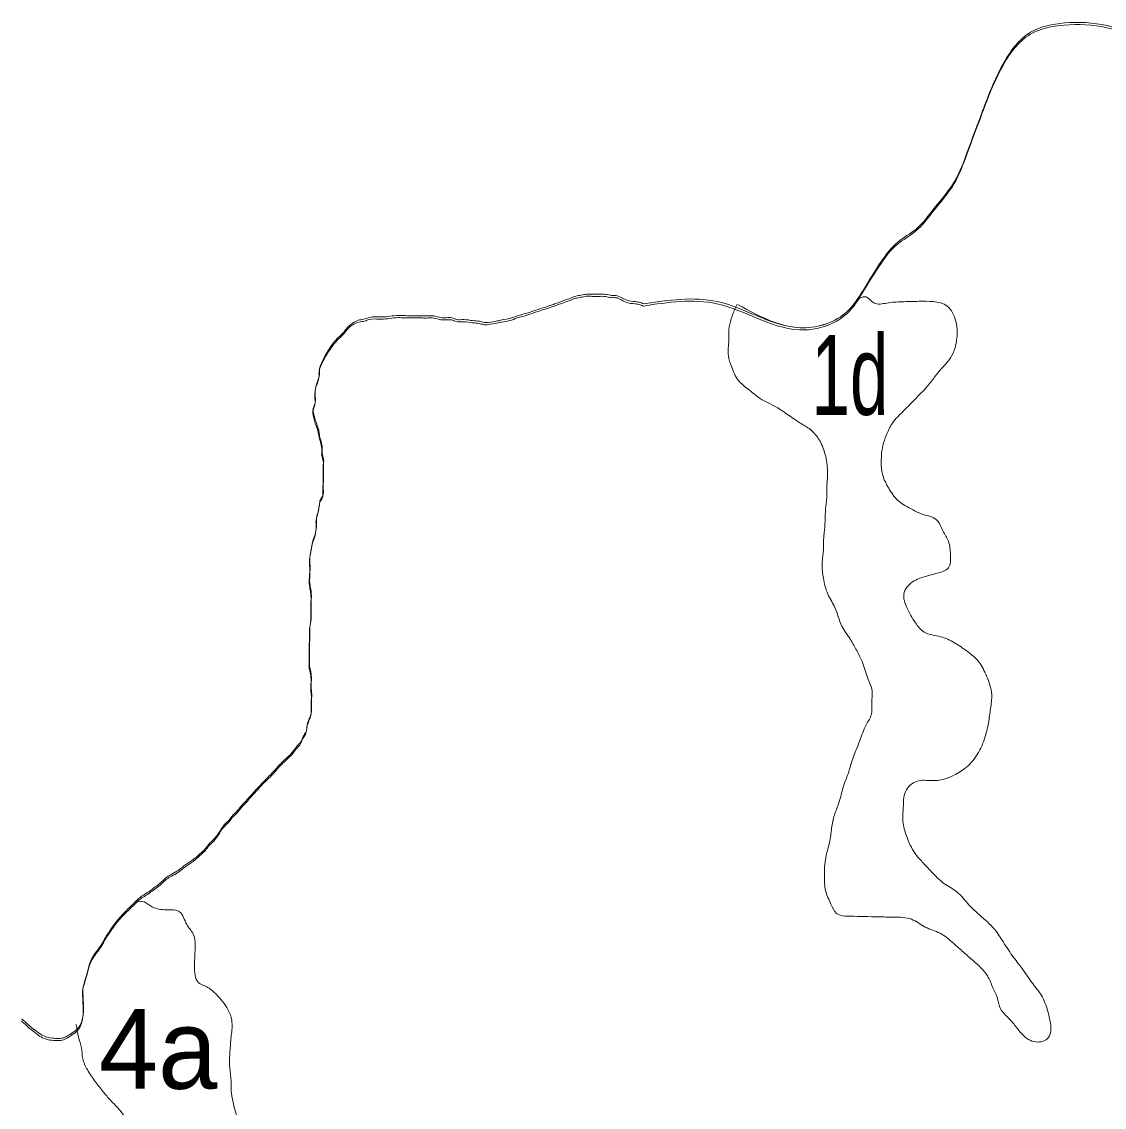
# Model space of a CAD drawing. Extents: x 854879 to 917879, y 8541948 to 8631048.
# Drawn here: x 877509 to 882670, y 8607550 to 8612725 of the extents above; entities that cross this region are included whole.
import ezdxf
from ezdxf.enums import TextEntityAlignment as Align

# ---------------------------------------------------------------- set-up
doc = ezdxf.new("R2010")
doc.units = 0
doc.header["$LTSCALE"] = 150
for name, color, linetype, lineweight in [('12', 7, 'Continuous', 13), ('40', 7, 'Continuous', 13), ('50', 7, 'Continuous', 13), ('59', 7, 'Continuous', 13)]:
    doc.layers.add(name, color=color, linetype=linetype, lineweight=lineweight)

msp = doc.modelspace()

# ---------------------------------------------------------------- linework, layer by layer
at = {"layer": '12'}
for points in [[(883458.2, 8611696.1), (883312.8, 8611690.2), (883254.5, 8611718.9), (883130.1, 8612194.4), (883075.4, 8612309.7), (882992.8, 8612435.6), (882922.5, 8612525.6), (882806.7, 8612646.7), (882682.3, 8612696.7), (882478.6, 8612709.3), (882317.4, 8612665.3), (882183, 8612509), (882088.6, 8612290.9), (882014.9, 8612093.1), (881954.6, 8611953.6), (881858.8, 8611827.3), (881770.9, 8611726.5), (881683.5, 8611663.8), (881605.9, 8611573), (881515, 8611428.8), (881452.8, 8611342.9), (881245.3, 8611256.2), (880823.3, 8611380.8), (880472, 8611369.8)], [(880472, 8611369.8), (880451.7, 8611377.7), (880431.4, 8611380.5), (880395.8, 8611386), (880368, 8611399.1), (880340.2, 8611409.6), (880319.8, 8611409.8), (880291.9, 8611415.2), (880258.8, 8611415.6), (880230.8, 8611415.9), (880200.3, 8611416.3), (880174.8, 8611411.4), (880149.3, 8611406.6), (880123.8, 8611396.7), (880095.6, 8611386.8), (880047.1, 8611369.5), (880026.7, 8611362.1), (880003.7, 8611354.7), (879957.7, 8611339.9), (879921.9, 8611327.6), (879870.8, 8611312.9), (879835.1, 8611300.5), (879796.8, 8611293.3), (879773.9, 8611288.5), (879733.1, 8611281.3), (879710.2, 8611281.5), (879689.9, 8611286.9), (879656.9, 8611289.8), (879616.2, 8611295.3), (879580.6, 8611295.8), (879557.8, 8611303.7), (879532.4, 8611303.9), (879506.9, 8611304.2), (879474, 8611312.2), (879438.3, 8611312.7), (879410.4, 8611313), (879367.1, 8611313.4), (879326.4, 8611313.9), (879293.3, 8611314.3), (879252.6, 8611309.6), (879211.8, 8611307.6), (879166, 8611305.5), (879143, 8611298.1), (879117.5, 8611293.3), (879092, 8611283.4), (879061.1, 8611258.2), (879037.9, 8611230.5), (879009.6, 8611202.7), (878988.9, 8611177.5), (878947.4, 8611111.6), (878934.3, 8611083.7), (878926.3, 8611053.2), (878926.1, 8611030.3), (878912.8, 8610987.1), (878907.4, 8610961.7), (878907, 8610928.5), (878904, 8610890.3), (878896.1, 8610867.4), (878903.3, 8610831.7), (878910.6, 8610803.5), (878922.8, 8610767.7), (878927.6, 8610739.6), (878934.9, 8610714), (878939.6, 8610683.4), (878939.3, 8610657.9), (878946.6, 8610629.7), (878946.4, 8610609.3), (878946.1, 8610586.4), (878945.6, 8610550.7), (878945.3, 8610520.1), (878944.9, 8610487), (878941.9, 8610453.8), (878931.5, 8610436.1), (878926.1, 8610410.7), (878920.7, 8610380.2), (878912.7, 8610349.6), (878912.2, 8610308.8), (878904, 8610265.6), (878893.4, 8610232.6), (878888, 8610202), (878882.5, 8610174), (878881.9, 8610120.5), (878881.5, 8610092.5), (878880.8, 8610036.4), (878885.6, 8610008.3), (878887.9, 8609987.8), (878887.5, 8609952.2), (878887.2, 8609929.2), (878886.8, 8609901.2), (878886.4, 8609865.5), (878880.9, 8609829.8)], [(878880.9, 8609829.8), (878880.5, 8609801.8), (878880.2, 8609773.8), (878879.9, 8609753.3), (878879.7, 8609730.4), (878879.3, 8609699.8), (878878.9, 8609669.2), (878878.7, 8609648.8), (878883.4, 8609623.3), (878888.1, 8609590.1), (878887.9, 8609569.7), (878887.4, 8609534), (878889.7, 8609511), (878889.4, 8609490.6), (878889.1, 8609465.1), (878888.8, 8609439.6), (878885.9, 8609411.6), (878875.5, 8609386.2), (878867.4, 8609353.2), (878862, 8609327.7), (878849.1, 8609307.5), (878838.6, 8609282.1), (878820.5, 8609261.9), (878794.7, 8609229.1), (878774.1, 8609208.9), (878756, 8609191.2), (878732.9, 8609168.6), (878717.4, 8609150.9), (878694.2, 8609125.6), (878660.7, 8609092.9), (878637.5, 8609067.6), (878616.9, 8609044.9), (878593.7, 8609019.7), (878575.6, 8608999.5), (878555, 8608976.8), (878531.7, 8608949), (878508.6, 8608926.3), (878495.6, 8608908.6), (878472.5, 8608885.9), (878446.5, 8608847.9), (878418.1, 8608812.6), (878400.1, 8608794.9), (878384.6, 8608774.7), (878364, 8608754.5), (878335.7, 8608729.4), (878312.6, 8608711.8), (878289.5, 8608696.7), (878253.5, 8608669.1), (878222.8, 8608651.6), (878199.7, 8608636.6), (878174, 8608613.9), (878125.2, 8608576.2), (878099.6, 8608558.6), (878076.5, 8608543.6), (878058.5, 8608528.5), (878037.9, 8608508.3), (878017.3, 8608488.2), (877996.7, 8608468), (877973.5, 8608442.8), (877952.8, 8608417.5), (877939.9, 8608399.8), (877921.7, 8608371.9), (877906.2, 8608349.2), (877895.8, 8608328.9), (877851.7, 8608265.6), (877841.3, 8608247.9), (877817.5, 8608174.2), (877804.3, 8608131), (877798.9, 8608105.6), (877798.6, 8608085.2), (877791.8, 8607945), (877776.2, 8607917.2), (877748, 8607894.5), (877724.9, 8607879.5), (877701.9, 8607869.6), (877676.4, 8607867.3), (877643.4, 8607870.2), (877615.5, 8607878.2), (877587.7, 8607893.8), (877567.5, 8607909.3), (877544.8, 8607927.4), (877524.7, 8607945.5), (877507.1, 8607961)]]:
    msp.add_spline(points, degree=3, dxfattribs=at)
at = {"layer": '40'}
for p, q in [((881512.6, 8611410.6), (881493.8, 8611403.1)), ((878053.3, 8608532), (878093.8, 8608529.1))]:
    msp.add_line(p, q, dxfattribs=at)
for points in [[(881493.8, 8611403.1), (881454.5, 8611353.2), (881247, 8611266.5), (880924, 8611376.2)], [(881952.8, 8609132.6), (882013.1, 8609170.9), (882070.3, 8609241.2), (882095.6, 8609296.2), (882117.9, 8609383.1), (882127.8, 8609450.3), (882133.7, 8609517.7), (882108.8, 8609605.7), (882071.4, 8609674.1), (882017.7, 8609722.9), (881955.9, 8609764.1), (881889.8, 8609793.4), (881811.7, 8609815), (881769.7, 8609859.7), (881728.5, 8609932.1), (881714.6, 8609995.9), (881755.8, 8610054.6), (881819.6, 8610080.9), (881871.2, 8610095.7), (881927.2, 8610122.2), (881936.8, 8610181.6), (881927, 8610249.3), (881900.9, 8610297.6), (881871, 8610349.9), (881797, 8610379.3), (881746.5, 8610404.3), (881692.3, 8610437.3), (881646.8, 8610494), (881617, 8610554.2), (881608.6, 8610665.6), (881618, 8610717.1), (881635.1, 8610764.3), (881660.2, 8610811.4), (881713.1, 8610869.8), (881774.1, 8610932), (881822.9, 8610982.5), (881859.7, 8611029.3), (881904.7, 8611083.9), (881937.3, 8611122.9), (881958.5, 8611170.1), (881968.6, 8611245.3), (881962.2, 8611297.1), (881921.1, 8611369.5), (881854.7, 8611390.9), (881787.8, 8611392.4), (881705, 8611390.3), (881633.9, 8611384), (881570.9, 8611385.4), (881528.5, 8611414.2), (881512.6, 8611410.6)], [(880919.7, 8611378), (880916.6, 8611372.4), (880895.4, 8611321.3), (880882, 8611270), (880880.1, 8611206.5), (880877.9, 8611131.1), (880892.2, 8611083.1), (880925.6, 8611014.8), (880971.7, 8610974), (881029.4, 8610929), (881107, 8610887.5), (881157.2, 8610854.6), (881219, 8610813.5), (881269.2, 8610780.6), (881311.1, 8610732), (881336.9, 8610671.8), (881350.3, 8610592.1), (881347.7, 8610504.7), (881345.8, 8610441.2), (881340.3, 8610389.7), (881338.5, 8610330.2), (881332.9, 8610274.7), (881330.6, 8610195.3), (881324.7, 8610131.9), (881330.8, 8610072.2), (881352.2, 8609996.2), (881385.8, 8609931.9), (881418.6, 8609843.8), (881460, 8609779.3), (881489.9, 8609727), (881516, 8609674.8), (881541.3, 8609598.7), (881563, 8609534.7), (881561.3, 8609479.1), (881559.7, 8609423.5), (881534.5, 8609372.5), (881504.7, 8609297.7), (881470.6, 8609211.1), (881448.8, 8609140.1), (881427.3, 8609081), (881405.3, 8609002.1), (881383.8, 8608943), (881370.1, 8608879.7), (881360.2, 8608812.4), (881342.3, 8608741.3), (881335.7, 8608650.1), (881341.5, 8608582.5), (881367.2, 8608518.3), (881393.5, 8608474.1), (881460, 8608460.6), (881527, 8608459.1), (881593.9, 8608457.6), (881664.8, 8608456), (881751.1, 8608446.1), (881817, 8608408.8), (881887, 8608379.4), (881952.5, 8608330.3), (881998.6, 8608289.5), (882044.6, 8608248.8), (882113.4, 8608175.7), (882139.3, 8608119.5), (882161.3, 8608067.4), (882175.7, 8608019.4), (882213.7, 8607974.8), (882251.8, 8607930.3), (882286.1, 8607889.8), (882352.2, 8607860.5), (882404, 8607883.1), (882413.9, 8607950.4), (882400, 8608010.3), (882370.6, 8608082.5), (882328.9, 8608139), (882283.6, 8608203.6), (882238.1, 8608264.2), (882189.1, 8608336.8), (882147.6, 8608397.3), (882074.8, 8608466.5), (882025, 8608515.3), (881967.7, 8608576.2), (881905.9, 8608617.3), (881844.6, 8608674.3), (881802.6, 8608719), (881768.3, 8608759.5), (881727.5, 8608843.8), (881709.9, 8608911.7), (881711.9, 8608979.2), (881722, 8609054.4), (881778.7, 8609104.8), (881845.7, 8609107.2), (881905, 8609113.8), (881952.8, 8609132.6)], [(878093.8, 8608529.1), (878132.5, 8608504.4), (878199.1, 8608491), (878261.8, 8608481.6), (878295.5, 8608421.3), (878325.7, 8608376.9), (878335.1, 8608297.3), (878332.8, 8608221.8), (878350.3, 8608146), (878396.8, 8608121.1), (878435.2, 8608088.4), (878492.2, 8608015.7), (878510.3, 8607963.6), (878508.2, 8607892.2), (878502.2, 8607824.8), (878500.1, 8607753.3), (878506.1, 8607689.7), (878508.1, 8607626.1), (878525.2, 8607538.3), (878546.4, 8607458.4), (878568.2, 8607394.3), (878602.4, 8607353.8), (878648.3, 8607309.1), (878753.2, 8607259.1), (878819.6, 8607237.7), (878893.9, 8607220.1), (878972, 8607198.5), (879026.5, 8607177.4), (879095.9, 8607124.2), (879082.3, 8607064.9), (879044.7, 8606994.2), (879023.1, 8606931.2), (879021.6, 8606879.6), (879047, 8606807.5), (879069, 8606751.4), (879067.1, 8606687.9), (879053.4, 8606624.7), (879028.3, 8606577.6), (878979.7, 8606531), (878924, 8606512.4), (878857.2, 8606517.9), (878798.8, 8606543.1), (878724, 8606544.8), (878676.2, 8606526), (878600.7, 8606503.9), (878545.6, 8606505.1), (878519.4, 8606553.4), (878497.7, 8606617.4), (878472, 8606681.6), (878441.7, 8606722), (878383.6, 8606755.1), (878329.3, 8606784.1), (878283.1, 8606816.9), (878249, 8606865.4), (878207.7, 8606933.8), (878185.5, 8606982), (878163.7, 8607042.1), (878145.8, 8607102.1), (878128, 8607166), (878106.6, 8607242), (878096.4, 8607293.8), (878075.1, 8607373.8), (878041.5, 8607434.1), (877977.5, 8607534.8), (877931.7, 8607583.5), (877897.4, 8607624), (877859.5, 8607672.6), (877821.8, 8607729), (877799.7, 8607781.2), (877793.3, 8607832.9), (877779.1, 8607884.9), (877769.1, 8607944.7)], [(877773.8, 8607923.6), (877777.9, 8607927.4), (877793.5, 8607955.3), (877800.3, 8608095.5), (877800.6, 8608115.9), (877806, 8608141.3), (877819.2, 8608184.5), (877843, 8608258.2), (877853.4, 8608275.9), (877897.5, 8608339.2), (877907.9, 8608359.4), (877923.4, 8608382.2), (877941.6, 8608410.1), (877954.5, 8608427.8), (877975.2, 8608453), (877998.4, 8608478.3), (878019, 8608498.4), (878039.6, 8608518.6), (878053.3, 8608532)]]:
    msp.add_spline(points, degree=3, dxfattribs=at)
at = {"layer": '50'}
for points in [[(883459.9, 8611706.3), (883314.5, 8611700.4), (883256.2, 8611729.2), (883131.8, 8612204.6), (883077.1, 8612320), (882994.5, 8612445.8), (882924.2, 8612535.8), (882808.4, 8612657), (882684, 8612706.9), (882480.2, 8612719.5), (882319.1, 8612675.6), (882184.7, 8612519.2), (882090.3, 8612301.2), (882016.6, 8612103.3), (881956.3, 8611963.9), (881860.5, 8611837.6), (881772.6, 8611736.7), (881685.2, 8611674.1), (881607.6, 8611583.3), (881516.7, 8611439.1), (881454.5, 8611353.2), (881247, 8611266.5), (880825, 8611391.1), (880473.7, 8611380.1)], [(880473.7, 8611380.1), (880453.4, 8611388), (880433.1, 8611390.8), (880397.6, 8611396.3), (880369.7, 8611409.3), (880341.9, 8611419.8), (880321.5, 8611420.1), (880293.6, 8611425.5), (880260.5, 8611425.9), (880232.5, 8611426.2), (880202, 8611426.5), (880176.5, 8611421.7), (880151, 8611416.9), (880125.5, 8611407), (880097.3, 8611397.1), (880048.8, 8611379.8), (880028.3, 8611372.4), (880005.4, 8611365), (879959.4, 8611350.2), (879923.6, 8611337.9), (879872.6, 8611323.1), (879836.8, 8611310.8), (879798.5, 8611303.6), (879775.6, 8611298.7), (879734.8, 8611291.5), (879711.9, 8611291.8), (879691.6, 8611297.1), (879658.6, 8611300.1), (879617.9, 8611305.6), (879582.3, 8611306), (879559.5, 8611313.9), (879534.1, 8611314.2), (879508.6, 8611314.5), (879475.7, 8611322.5), (879440, 8611322.9), (879412.1, 8611323.2), (879368.8, 8611323.7), (879328.1, 8611324.2), (879295, 8611324.5), (879254.3, 8611319.9), (879213.5, 8611317.8), (879167.7, 8611315.8), (879144.7, 8611308.4), (879119.2, 8611303.6), (879093.7, 8611293.7), (879062.8, 8611268.5), (879039.6, 8611240.7), (879011.3, 8611213), (878990.6, 8611187.7), (878949.1, 8611121.9), (878936, 8611094), (878928, 8611063.5), (878927.8, 8611040.6), (878914.5, 8610997.3), (878909.1, 8610971.9), (878908.7, 8610938.8), (878905.7, 8610900.6), (878897.8, 8610877.7), (878905, 8610841.9), (878912.3, 8610813.8), (878924.6, 8610778), (878929.3, 8610749.8), (878936.6, 8610724.3), (878941.3, 8610693.6), (878941, 8610668.1), (878948.3, 8610640), (878948.1, 8610619.6), (878947.8, 8610596.7), (878947.3, 8610561), (878947, 8610530.4), (878946.6, 8610497.2), (878943.6, 8610464.1), (878933.2, 8610446.4), (878927.8, 8610420.9), (878922.4, 8610390.4), (878914.4, 8610359.9), (878913.9, 8610319.1), (878905.7, 8610275.8), (878895.1, 8610242.8), (878889.7, 8610212.3), (878884.2, 8610184.3), (878883.6, 8610130.8), (878883.2, 8610102.7), (878882.5, 8610046.6), (878887.3, 8610018.5), (878889.6, 8609998.1), (878889.2, 8609962.4), (878888.9, 8609939.5), (878888.5, 8609911.4), (878888.1, 8609875.7), (878882.6, 8609840.1)], [(878882.6, 8609840.1), (878882.2, 8609812.1), (878881.9, 8609784), (878881.6, 8609763.6), (878881.3, 8609740.7), (878881, 8609710.1), (878880.6, 8609679.5), (878880.4, 8609659.1), (878885.1, 8609633.5), (878889.8, 8609600.3), (878889.6, 8609579.9), (878889.1, 8609544.2), (878891.4, 8609521.3), (878891.1, 8609500.9), (878890.8, 8609475.4), (878890.5, 8609449.9), (878887.6, 8609421.9), (878877.2, 8609396.5), (878869.1, 8609363.4), (878863.7, 8609338), (878850.8, 8609317.7), (878840.3, 8609292.4), (878822.2, 8609272.2), (878796.4, 8609239.3), (878775.8, 8609219.1), (878757.7, 8609201.5), (878734.6, 8609178.8), (878719.1, 8609161.1), (878695.9, 8609135.9), (878662.4, 8609103.1), (878639.2, 8609077.9), (878618.6, 8609055.2), (878595.4, 8609029.9), (878577.3, 8609009.8), (878556.7, 8608987), (878533.4, 8608959.2), (878510.3, 8608936.6), (878497.3, 8608918.8), (878474.2, 8608896.2), (878448.2, 8608858.2), (878419.8, 8608822.8), (878401.8, 8608805.2), (878386.3, 8608785), (878365.7, 8608764.8), (878337.4, 8608739.6), (878314.3, 8608722), (878291.2, 8608707), (878255.2, 8608679.3), (878224.5, 8608661.8), (878201.4, 8608646.8), (878175.7, 8608624.2), (878126.9, 8608586.4), (878101.2, 8608568.9), (878078.2, 8608553.8), (878060.2, 8608538.8), (878039.6, 8608518.6), (878019, 8608498.4), (877998.4, 8608478.3), (877975.2, 8608453), (877954.5, 8608427.8), (877941.6, 8608410.1), (877923.4, 8608382.2), (877907.9, 8608359.4), (877897.5, 8608339.2), (877853.4, 8608275.9), (877843, 8608258.2), (877819.2, 8608184.5), (877806, 8608141.3), (877800.6, 8608115.9), (877800.3, 8608095.5), (877793.5, 8607955.3), (877777.9, 8607927.4), (877749.7, 8607904.8), (877726.6, 8607889.8), (877703.6, 8607879.8), (877678.1, 8607877.6), (877645.1, 8607880.5), (877617.2, 8607888.4), (877589.4, 8607904.1), (877569.2, 8607919.6), (877546.5, 8607937.7), (877526.4, 8607955.8), (877508.8, 8607971.3)]]:
    msp.add_spline(points, degree=3, dxfattribs=at)

# ---------------------------------------------------------------- texts
at = {"layer": '59', "width": 0.65}
msp.add_text('1d', height=380, dxfattribs=at).set_placement((881457.5, 8610851.1), align=Align.CENTER)
at = {"layer": '59'}
msp.add_text('4a', height=380, dxfattribs=at).set_placement((878159, 8607637.8), align=Align.CENTER)

doc.saveas('drawing.dxf')
